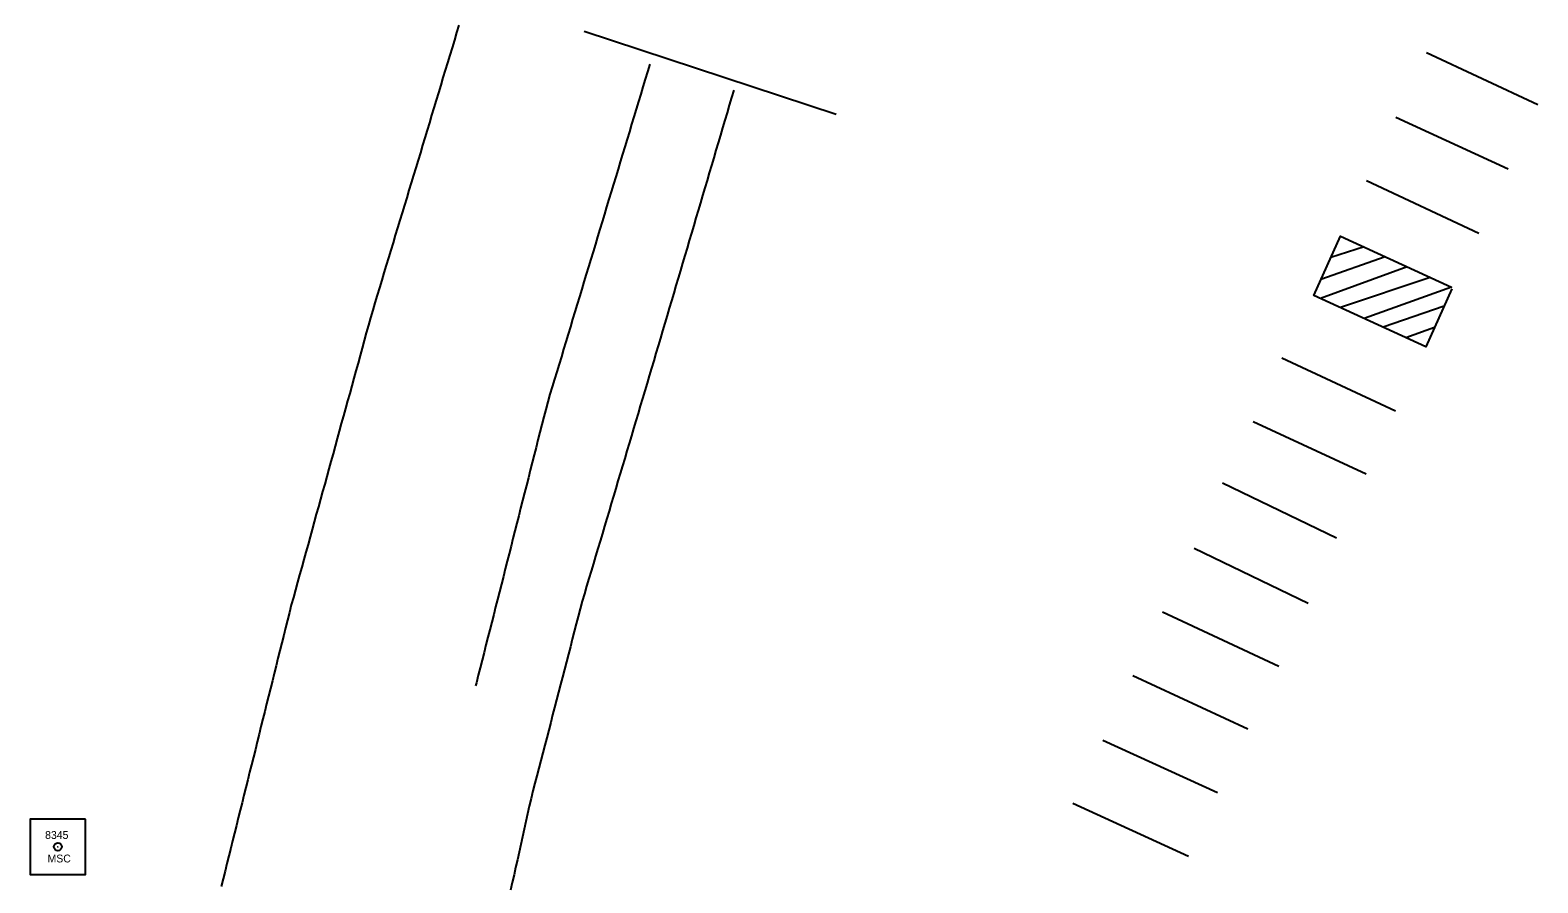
# Model space of a CAD drawing. Extents: x 205929 to 2357175, y -1785700 to 846739.
# Drawn here: x 2017599.9 to 2017792.3, y 817801.3 to 817910.1 of the extents above; entities that cross this region are included whole.
import ezdxf

# ---------------------------------------------------------------- set-up
doc = ezdxf.new("R2010")
doc.units = 0
for name, color, linetype in [('RD_HC_Survey', 7, 'Continuous'), ('RD_HC_txCode', 7, 'Continuous'), ('RD_Sketch1', 7, 'Continuous'), ('RD_SMD_Locator', 7, 'Continuous')]:
    doc.layers.add(name, color=color, linetype=linetype)

msp = doc.modelspace()

# ---------------------------------------------------------------- linework, layer by layer
at = {"layer": 'RD_HC_Survey'}
msp.add_lwpolyline([(2017606.97, 817809.46), (2017599.9, 817809.46), (2017599.9, 817802.39), (2017606.97, 817802.39)], close=True, dxfattribs=at)
msp.add_circle((2017603.44, 817805.93), 0.5, dxfattribs=at)
at = {"layer": 'RD_Sketch1'}
for points in [[(2017654.6, 817910.73), (2017654.31, 817909.78), (2017654.02, 817908.82), (2017653.73, 817907.86), (2017653.44, 817906.91), (2017653.15, 817905.95), (2017652.86, 817904.99), (2017652.57, 817904.04), (2017652.28, 817903.08), (2017651.99, 817902.12), (2017651.7, 817901.16), (2017651.41, 817900.21), (2017651.12, 817899.25), (2017650.83, 817898.29), (2017650.54, 817897.34), (2017650.25, 817896.38), (2017649.96, 817895.42), (2017649.68, 817894.47), (2017649.39, 817893.51), (2017649.1, 817892.55), (2017648.81, 817891.6), (2017648.52, 817890.64), (2017648.23, 817889.68), (2017647.94, 817888.73), (2017647.65, 817887.77), (2017647.36, 817886.81), (2017647.07, 817885.86), (2017646.78, 817884.9), (2017646.49, 817883.94), (2017646.2, 817882.98), (2017645.91, 817882.03), (2017645.62, 817881.07), (2017645.33, 817880.11), (2017645.04, 817879.16), (2017644.75, 817878.2), (2017644.46, 817877.24), (2017644.17, 817876.29), (2017643.88, 817875.33), (2017643.6, 817874.37), (2017643.33, 817873.41), (2017643.06, 817872.45), (2017642.79, 817871.48), (2017642.53, 817870.52), (2017642.26, 817869.55), (2017642, 817868.59), (2017641.73, 817867.63), (2017641.46, 817866.66), (2017641.2, 817865.7), (2017640.93, 817864.73), (2017640.67, 817863.77), (2017640.4, 817862.81), (2017640.13, 817861.84), (2017639.87, 817860.88), (2017639.6, 817859.91), (2017639.34, 817858.95), (2017639.07, 817857.99), (2017638.81, 817857.02), (2017638.54, 817856.06), (2017638.27, 817855.09), (2017638.01, 817854.13), (2017637.74, 817853.17), (2017637.48, 817852.2), (2017637.21, 817851.24), (2017636.94, 817850.27), (2017636.68, 817849.31), (2017636.41, 817848.35), (2017636.15, 817847.38), (2017635.88, 817846.42), (2017635.61, 817845.45), (2017635.35, 817844.49), (2017635.08, 817843.53), (2017634.82, 817842.56), (2017634.55, 817841.6), (2017634.28, 817840.63), (2017634.02, 817839.67), (2017633.75, 817838.71), (2017633.49, 817837.74), (2017633.22, 817836.78), (2017632.97, 817835.81), (2017632.73, 817834.84), (2017632.49, 817833.87), (2017632.25, 817832.9), (2017632, 817831.93), (2017631.76, 817830.96), (2017631.52, 817829.99), (2017631.28, 817829.02), (2017631.04, 817828.05), (2017630.8, 817827.08), (2017630.56, 817826.11), (2017630.32, 817825.14), (2017630.07, 817824.17), (2017629.83, 817823.2), (2017629.59, 817822.23), (2017629.35, 817821.25), (2017629.11, 817820.28), (2017628.87, 817819.31), (2017628.63, 817818.34), (2017628.39, 817817.37), (2017628.14, 817816.4), (2017627.9, 817815.43), (2017627.66, 817814.46), (2017627.42, 817813.49), (2017627.18, 817812.52), (2017626.94, 817811.55), (2017626.7, 817810.58), (2017626.46, 817809.61), (2017626.21, 817808.64), (2017625.97, 817807.67), (2017625.73, 817806.7), (2017625.49, 817805.73), (2017625.25, 817804.76), (2017625.01, 817803.79), (2017624.77, 817802.82), (2017624.53, 817801.85), (2017624.28, 817800.88)], [(2017670.57, 817909.98), (2017702.74, 817899.37)], [(2017778.04, 817907.23), (2017792.25, 817900.6)], [(2017678.95, 817905.76), (2017678.66, 817904.8), (2017678.37, 817903.85), (2017678.08, 817902.89), (2017677.79, 817901.93), (2017677.5, 817900.98), (2017677.21, 817900.02), (2017676.93, 817899.06), (2017676.64, 817898.1), (2017676.35, 817897.15), (2017676.06, 817896.19), (2017675.77, 817895.23), (2017675.48, 817894.28), (2017675.19, 817893.32), (2017674.9, 817892.36), (2017674.61, 817891.4), (2017674.32, 817890.45), (2017674.03, 817889.49), (2017673.74, 817888.53), (2017673.45, 817887.58), (2017673.16, 817886.62), (2017672.88, 817885.66), (2017672.59, 817884.7), (2017672.3, 817883.75), (2017672.01, 817882.79), (2017671.72, 817881.83), (2017671.43, 817880.88), (2017671.14, 817879.92), (2017670.85, 817878.96), (2017670.56, 817878), (2017670.27, 817877.05), (2017669.98, 817876.09), (2017669.69, 817875.13), (2017669.4, 817874.18), (2017669.11, 817873.22), (2017668.83, 817872.26), (2017668.54, 817871.3), (2017668.25, 817870.35), (2017667.96, 817869.39), (2017667.67, 817868.43), (2017667.38, 817867.48), (2017667.09, 817866.52), (2017667.09, 817866.52), (2017666.8, 817865.56), (2017666.51, 817864.6), (2017666.22, 817863.65), (2017665.93, 817862.69), (2017665.67, 817861.72), (2017665.43, 817860.76), (2017665.18, 817859.79), (2017664.94, 817858.82), (2017664.69, 817857.85), (2017664.45, 817856.88), (2017664.2, 817855.91), (2017663.95, 817854.94), (2017663.71, 817853.97), (2017663.46, 817853), (2017663.22, 817852.03), (2017662.97, 817851.06), (2017662.73, 817850.09), (2017662.48, 817849.12), (2017662.23, 817848.15), (2017661.99, 817847.19), (2017661.74, 817846.22), (2017661.5, 817845.25), (2017661.25, 817844.28), (2017661, 817843.31), (2017660.76, 817842.34), (2017660.51, 817841.37), (2017660.27, 817840.4), (2017660.02, 817839.43), (2017659.78, 817838.46), (2017659.53, 817837.49), (2017659.28, 817836.52), (2017659.04, 817835.55), (2017658.79, 817834.58), (2017658.55, 817833.62), (2017658.3, 817832.65), (2017658.05, 817831.68), (2017657.81, 817830.71), (2017657.56, 817829.74), (2017657.32, 817828.77), (2017657.07, 817827.8), (2017656.83, 817826.83), (2017656.73, 817826.46)], [(2017689.66, 817902.44), (2017689.37, 817901.49), (2017689.09, 817900.53), (2017688.81, 817899.57), (2017688.52, 817898.61), (2017688.24, 817897.65), (2017687.96, 817896.69), (2017687.67, 817895.73), (2017687.39, 817894.77), (2017687.11, 817893.81), (2017686.82, 817892.85), (2017686.54, 817891.9), (2017686.26, 817890.94), (2017685.97, 817889.98), (2017685.69, 817889.02), (2017685.41, 817888.06), (2017685.12, 817887.1), (2017684.84, 817886.14), (2017684.56, 817885.18), (2017684.27, 817884.22), (2017683.99, 817883.26), (2017683.71, 817882.31), (2017683.42, 817881.35), (2017683.14, 817880.39), (2017682.86, 817879.43), (2017682.57, 817878.47), (2017682.29, 817877.51), (2017682.01, 817876.55), (2017681.72, 817875.59), (2017681.44, 817874.63), (2017681.16, 817873.68), (2017680.87, 817872.72), (2017680.59, 817871.76), (2017680.31, 817870.8), (2017680.02, 817869.84), (2017679.74, 817868.88), (2017679.45, 817867.92), (2017679.17, 817866.96), (2017678.88, 817866.01), (2017678.6, 817865.05), (2017678.31, 817864.09), (2017678.03, 817863.13), (2017677.74, 817862.17), (2017677.46, 817861.21), (2017677.17, 817860.26), (2017676.89, 817859.3), (2017676.6, 817858.34), (2017676.32, 817857.38), (2017676.03, 817856.42), (2017675.75, 817855.46), (2017675.46, 817854.51), (2017675.18, 817853.55), (2017674.89, 817852.59), (2017674.61, 817851.63), (2017674.32, 817850.67), (2017674.04, 817849.71), (2017673.75, 817848.76), (2017673.47, 817847.8), (2017673.18, 817846.84), (2017672.9, 817845.88), (2017672.61, 817844.92), (2017672.33, 817843.96), (2017672.04, 817843.01), (2017671.76, 817842.05), (2017671.47, 817841.09), (2017671.19, 817840.13), (2017670.9, 817839.17), (2017670.62, 817838.21), (2017670.33, 817837.25), (2017670.08, 817836.29), (2017669.83, 817835.32), (2017669.57, 817834.35), (2017669.32, 817833.38), (2017669.07, 817832.42), (2017668.82, 817831.45), (2017668.57, 817830.48), (2017668.32, 817829.51), (2017668.07, 817828.54), (2017667.81, 817827.58), (2017667.56, 817826.61), (2017667.31, 817825.64), (2017667.06, 817824.67), (2017666.81, 817823.71), (2017666.56, 817822.74), (2017666.31, 817821.77), (2017666.06, 817820.8), (2017665.8, 817819.83), (2017665.55, 817818.87), (2017665.3, 817817.9), (2017665.05, 817816.93), (2017664.8, 817815.96), (2017664.55, 817814.99), (2017664.3, 817814.03), (2017664.04, 817813.06), (2017663.8, 817812.09), (2017663.58, 817811.11), (2017663.36, 817810.14), (2017663.15, 817809.16), (2017662.93, 817808.19), (2017662.71, 817807.21), (2017662.49, 817806.23), (2017662.28, 817805.26), (2017662.06, 817804.28), (2017661.84, 817803.3), (2017661.63, 817802.33), (2017661.41, 817801.35), (2017661.19, 817800.38)], [(2017774.14, 817899.02), (2017788.45, 817892.41)], [(2017770.41, 817890.92), (2017784.7, 817884.22)], [(2017781.28, 817877.12), (2017777.96, 817869.7), (2017763.65, 817876.27), (2017767.08, 817883.82), (2017781.23, 817877.3), (2017770.11, 817873.31)], [(2017770.08, 817882.44), (2017765.83, 817881.08)], [(2017775.57, 817879.91), (2017764.52, 817875.87)], [(2017772.77, 817881.2), (2017764.57, 817878.29)], [(2017778.5, 817878.56), (2017767.06, 817874.7)], [(2017780.28, 817874.9), (2017772.51, 817872.2)], [(2017779.06, 817872.17), (2017775.4, 817870.87)], [(2017774.09, 817861.48), (2017759.59, 817868.25)], [(2017770.35, 817853.47), (2017755.91, 817860.14)], [(2017766.57, 817845.3), (2017752, 817852.31)], [(2017762.94, 817836.94), (2017748.39, 817843.97)], [(2017759.2, 817828.93), (2017744.38, 817835.86)], [(2017755.23, 817820.91), (2017740.58, 817827.72)], [(2017751.4, 817812.8), (2017736.76, 817819.5)], [(2017747.67, 817804.69), (2017732.92, 817811.43)]]:
    msp.add_lwpolyline(points, dxfattribs=at)
at = {"layer": 'RD_SMD_Locator'}
msp.add_circle((2017603.44, 817805.93), 0.001, dxfattribs=at)

# ---------------------------------------------------------------- texts
at = {"layer": 'RD_HC_txCode'}
for s, p in [('8345', (2017601.81, 817806.93)), ('MSC', (2017602.12, 817803.93))]:
    msp.add_text(s, height=1, dxfattribs=at).set_placement(p)

doc.saveas('drawing.dxf')
